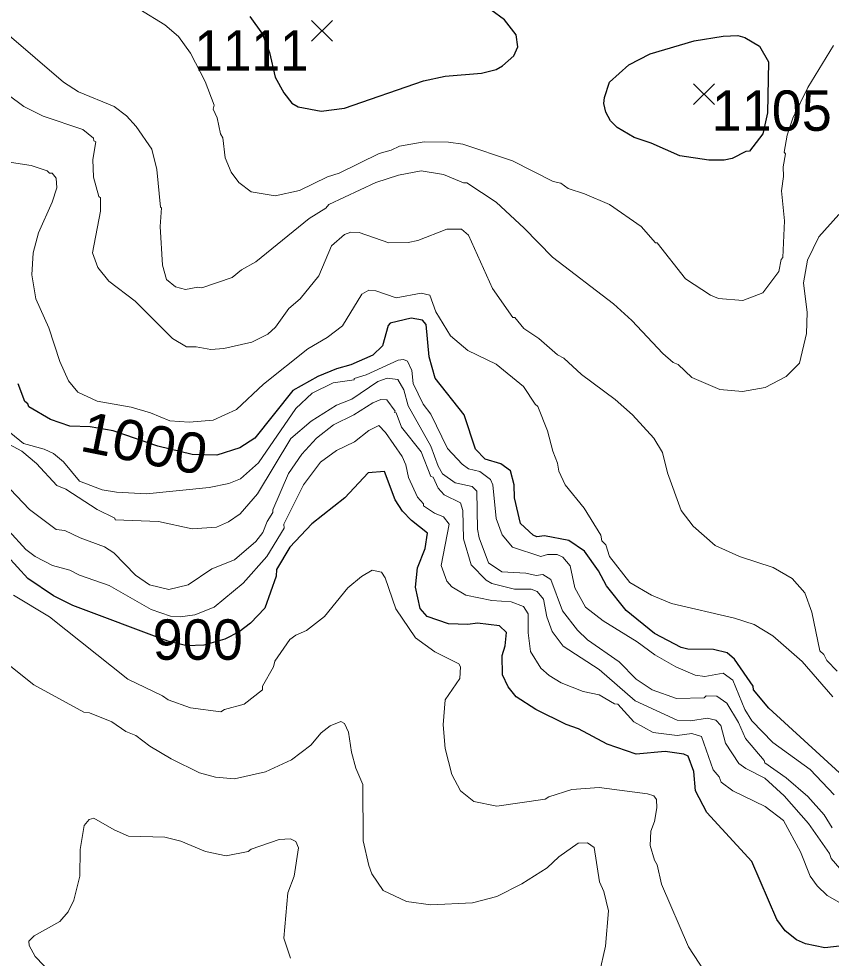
# Model space of a CAD drawing. Extents: x 265.7 to 292.1, y 7676.2 to 7704.2.
# Drawn here: x 267.081 to 268.69, y 7696.571 to 7698.433 of the extents above; entities that cross this region are included whole.
import ezdxf
from ezdxf.enums import TextEntityAlignment as Align

# ---------------------------------------------------------------- set-up
doc = ezdxf.new("R2010")
doc.units = 0
doc.header["$LTSCALE"] = 0.032
for name, color, linetype, lineweight in [('1', 7, 'Continuous', 25), ('2', 7, 'Continuous', 13), ('21', 7, 'Continuous', 25)]:
    doc.layers.add(name, color=color, linetype=linetype, lineweight=lineweight)
doc.layers.add('61', color=7, linetype='Continuous')

msp = doc.modelspace()

# ---------------------------------------------------------------- linework, layer by layer
at = {"layer": '1'}
for points in [[(267.5381, 7698.4374), (267.5632, 7698.4023), (267.5774, 7698.3663), (267.5883, 7698.317), (267.6052, 7698.2862), (267.6212, 7698.2654), (267.634, 7698.2583), (267.6795, 7698.2495), (267.7257, 7698.2559), (267.8821, 7698.3101), (267.9252, 7698.3189), (267.9971, 7698.3253), (268.0258, 7698.3325), (268.0385, 7698.3397), (268.0609, 7698.3596), (268.0689, 7698.3772), (268.0657, 7698.4011), (268.0425, 7698.4306), (268.0154, 7698.4506)], [(268.7064, 7696.9384), (268.566, 7697.0661), (268.5357, 7697.1028), (268.5349, 7697.11), (268.4982, 7697.1635), (268.4838, 7697.1762), (268.4567, 7697.1826), (268.4056, 7697.1834), (268.3928, 7697.1866), (268.3394, 7697.2145), (268.2835, 7697.26), (268.2444, 7697.3087), (268.2285, 7697.3382), (268.2013, 7697.3773), (268.1702, 7697.3989), (268.1215, 7697.4076), (268.1064, 7697.406), (268.0992, 7697.4092), (268.0745, 7697.4324), (268.0625, 7697.4835), (268.0617, 7697.509), (268.0545, 7697.5369), (268.0354, 7697.5505), (268.0042, 7697.5601), (267.9851, 7697.58), (267.9627, 7697.6478), (267.9053, 7697.7205), (267.8933, 7697.7627), (267.8877, 7697.8266), (267.8805, 7697.8353), (267.8574, 7697.8393), (267.8159, 7697.8298), (267.8119, 7697.825), (267.8007, 7697.7843), (267.7816, 7697.7659), (267.7385, 7697.7468), (267.7098, 7697.7388), (267.6731, 7697.7236), (267.6236, 7697.6957), (267.5478, 7697.6016), (267.5183, 7697.5824), (267.4728, 7697.568), (267.4237, 7697.5689), (267.3559, 7697.5859), (267.2673, 7697.6161), (267.2221, 7697.6237), (267.1815, 7697.6255), (267.1432, 7697.6382), (267.1001, 7697.6638), (267.0985, 7697.6694), (267.0922, 7697.6742), (267.0794, 7697.7093)], [(268.7344, 7696.5977), (268.6769, 7696.5913), (268.6386, 7696.5993), (268.6211, 7696.6073), (268.5987, 7696.6248), (268.5819, 7696.6472), (268.5325, 7696.7621), (268.4431, 7696.8594), (268.4208, 7696.9025), (268.4176, 7696.9408), (268.4064, 7696.9712), (268.3976, 7696.9752), (268.3609, 7696.9807), (268.3035, 7696.9751), (268.246, 7696.9951), (268.1894, 7697.0254), (268.1646, 7697.0342), (268.1048, 7697.0637), (268.0657, 7697.0885), (268.0497, 7697.1084), (268.0385, 7697.1324), (268.0377, 7697.1707), (268.0441, 7697.1898), (268.0465, 7697.2161), (268.033, 7697.2297), (267.9891, 7697.2345), (267.9699, 7697.2321), (267.9316, 7697.2337), (267.8893, 7697.248), (267.8758, 7697.264), (267.8662, 7697.3063), (267.8702, 7697.3446), (267.8853, 7697.3829), (267.8901, 7697.4132), (267.8582, 7697.438), (267.8406, 7697.4571), (267.8263, 7697.4795), (267.8047, 7697.5353), (267.7728, 7697.5329), (267.7265, 7697.4835), (267.6611, 7697.4316), (267.6172, 7697.3853), (267.5909, 7697.3414), (267.5901, 7697.3279), (267.5677, 7697.2648), (267.5396, 7697.2349), (267.517, 7697.2179), (267.4887, 7697.2028), (267.4473, 7697.1915), (267.4133, 7697.1896), (267.3757, 7697.199), (267.1879, 7697.2696), (267.1496, 7697.2887), (267.0985, 7697.3231), (267.0363, 7697.3909)]]:
    msp.add_lwpolyline(points, dxfattribs=at)
msp.add_lwpolyline([(268.5634, 7698.2464), (268.5543, 7698.2047), (268.5277, 7698.1705), (268.5205, 7698.1697), (268.4934, 7698.1561), (268.4774, 7698.1529), (268.4471, 7698.1529), (268.3897, 7698.1609), (268.333, 7698.1864), (268.2995, 7698.1976), (268.266, 7698.2176), (268.2524, 7698.2303), (268.2436, 7698.2479), (268.2396, 7698.2647), (268.2404, 7698.2766), (268.2508, 7698.307), (268.2891, 7698.3413), (268.3314, 7698.3636), (268.4184, 7698.3891), (268.4758, 7698.3987), (268.5046, 7698.3995), (268.5189, 7698.3955), (268.5476, 7698.3788), (268.5652, 7698.3476)], close=True, dxfattribs=at)
at = {"layer": '2'}
for points in [[(267.3906, 7697.9016), (267.373, 7697.916), (267.3651, 7697.9447), (267.3603, 7698.0213), (267.3635, 7698.058), (267.3611, 7698.0596), (267.3539, 7698.1338), (267.3443, 7698.1745), (267.3132, 7698.2192), (267.294, 7698.2407), (267.2693, 7698.2591), (267.1991, 7698.2878), (267.1688, 7698.307), (267.057, 7698.4035), (267.0124, 7698.4378)], [(267.6364, 7698.0923), (267.5885, 7698.0819), (267.5406, 7698.0899), (267.5167, 7698.1083), (267.5015, 7698.129), (267.4895, 7698.1569), (267.4848, 7698.1968), (267.48, 7698.2048), (267.4736, 7698.2367), (267.4656, 7698.2535), (267.4672, 7698.2615), (267.4496, 7698.3086), (267.4209, 7698.3644), (267.397, 7698.3979), (267.3699, 7698.4211), (267.3204, 7698.4514)], [(268.6945, 7698.3796), (268.6434, 7698.2966), (268.6134, 7698.2361), (268.6022, 7698.2023), (268.5965, 7698.1686), (268.5995, 7698.1649), (268.5947, 7698.1394), (268.5955, 7698.1202), (268.5915, 7698.0915), (268.5971, 7698.0325), (268.5939, 7697.9598), (268.5907, 7697.9559), (268.5859, 7697.9319), (268.554, 7697.8896), (268.5149, 7697.8745), (268.4663, 7697.8784), (268.4503, 7697.8848), (268.4008, 7697.9175), (268.345, 7697.9886), (268.3418, 7697.9886), (268.313, 7698.0213), (268.2508, 7698.0644), (268.2013, 7698.0859), (268.1686, 7698.0963), (268.1542, 7698.1067), (268.1391, 7698.1106), (268.0585, 7698.1513), (267.9603, 7698.1841), (267.9316, 7698.1881), (267.8837, 7698.1888)], [(268.7017, 7697.1395), (268.6809, 7697.1611), (268.6753, 7697.173), (268.6673, 7697.1802), (268.6514, 7697.2568), (268.6378, 7697.2951), (268.6123, 7697.3231), (268.5748, 7697.3454), (268.5078, 7697.367), (268.4599, 7697.3885), (268.416, 7697.4268), (268.3928, 7697.4579), (268.3657, 7697.5329), (268.3553, 7697.5728), (268.3386, 7697.6016), (268.2963, 7697.6478), (268.262, 7697.6782), (268.1949, 7697.7276), (268.1598, 7697.7603), (268.1479, 7697.7667), (268.1104, 7697.7994), (268.0808, 7697.8186), (268.0633, 7697.8409), (268.0593, 7697.8409), (268.0186, 7697.8984), (267.9715, 7698.0037), (267.9572, 7698.0157), (267.9284, 7698.0157), (267.871, 7697.9933), (267.8518, 7697.9894), (267.8135, 7697.9886), (267.7545, 7698.0093), (267.7385, 7698.0101), (267.7257, 7698.0053), (267.7002, 7697.983), (267.6747, 7697.9231), (267.638, 7697.8776), (267.6156, 7697.8585), (267.5893, 7697.8218), (267.5741, 7697.8074), (267.5422, 7697.7915), (267.4864, 7697.7795), (267.4608, 7697.7771), (267.4321, 7697.7827), (267.4129, 7697.7827), (267.385, 7697.7994), (267.3108, 7697.8729), (267.2589, 7697.9128), (267.2374, 7697.9399), (267.2262, 7697.9686), (267.2422, 7698.0516), (267.2422, 7698.0779), (267.239, 7698.0803), (267.2286, 7698.1186), (267.227, 7698.1537), (267.2334, 7698.1889), (267.2294, 7698.1912), (267.2286, 7698.196), (267.2071, 7698.2136), (267.1289, 7698.2399), (267.0906, 7698.2591), (267.0275, 7698.3054)], [(267.8837, 7698.1888), (267.8343, 7698.1801), (267.8183, 7698.1721), (267.7944, 7698.1657), (267.7154, 7698.1266), (267.6922, 7698.1194), (267.6364, 7698.0923)], [(268.2436, 7697.3901), (268.2356, 7697.3981), (268.2332, 7697.4092), (268.2005, 7697.4627), (268.163, 7697.509), (268.1503, 7697.5361), (268.1479, 7697.5521), (268.1383, 7697.576), (268.1279, 7697.6159), (268.1088, 7697.6646), (268.1032, 7697.6686), (268.08, 7697.7037), (268.0258, 7697.7484), (267.9699, 7697.7755), (267.9356, 7697.8042), (267.9069, 7697.8521), (267.8949, 7697.8848), (267.8774, 7697.8888), (267.8279, 7697.88), (267.788, 7697.8936), (267.7736, 7697.8952), (267.7601, 7697.8872), (267.7217, 7697.8242), (267.6914, 7697.801), (267.6531, 7697.7787), (267.5654, 7697.7085), (267.5119, 7697.6582), (267.4656, 7697.6375), (267.4177, 7697.6335), (267.3794, 7697.6359), (267.3411, 7697.6518), (267.3028, 7697.663), (267.2358, 7697.675), (267.1975, 7697.6925), (267.1791, 7697.7149), (267.1616, 7697.7532), (267.14, 7697.8202), (267.1145, 7697.8777), (267.1065, 7697.9255), (267.1089, 7697.9686), (267.1193, 7698.0085), (267.1464, 7698.0692), (267.156, 7698.0979), (267.1544, 7698.117), (267.1464, 7698.1266), (267.1416, 7698.1266), (267.1368, 7698.1314), (267.1049, 7698.1418), (267.0491, 7698.1505)], [(268.7048, 7698.0452), (268.6649, 7698.0005), (268.6426, 7697.9543), (268.6346, 7697.9096), (268.6418, 7697.8505), (268.641, 7697.809), (268.6266, 7697.75), (268.6003, 7697.7236), (268.5588, 7697.7021), (268.5141, 7697.6941), (268.4694, 7697.6981), (268.4136, 7697.722), (268.3865, 7697.7476), (268.3769, 7697.7516), (268.3561, 7697.7691), (268.2947, 7697.8346), (268.2588, 7697.8681), (268.1375, 7697.9606), (268.0816, 7698.0181), (268.0258, 7698.0692), (267.9683, 7698.1075), (267.9611, 7698.1075), (267.922, 7698.1242), (267.8774, 7698.1314), (267.8327, 7698.1226), (267.788, 7698.1083), (267.6946, 7698.0644), (267.689, 7698.0572), (267.6555, 7698.0372), (267.5502, 7697.9511)], [(267.5502, 7697.9511), (267.5215, 7697.9351), (267.5031, 7697.9199), (267.4433, 7697.8992), (267.4353, 7697.9008), (267.4106, 7697.896), (267.3906, 7697.9016)], [(267.7449, 7697.7173), (267.7449, 7697.7197), (267.7688, 7697.7268), (267.8319, 7697.7564), (267.8423, 7697.7572), (267.8502, 7697.754), (267.859, 7697.7356)], [(267.859, 7697.7356), (267.8614, 7697.7101), (267.8813, 7697.6686), (267.8965, 7697.6494), (267.93, 7697.5808), (267.9587, 7697.5497), (267.9715, 7697.5409), (267.9939, 7697.5353), (268.0146, 7697.5194), (268.0194, 7697.509), (268.0258, 7697.442), (268.0377, 7697.41), (268.0585, 7697.3853), (268.1143, 7697.3669), (268.1279, 7697.3709), (268.1471, 7697.3709), (268.1582, 7697.3654), (268.1726, 7697.3486), (268.1822, 7697.3047), (268.2029, 7697.2664), (268.238, 7697.2393), (268.3051, 7697.1978), (268.3402, 7697.1722), (268.3817, 7697.1483), (268.42, 7697.1316), (268.4391, 7697.1292), (268.4758, 7697.1355), (268.495, 7697.122), (268.5189, 7697.0637), (268.5325, 7697.0414), (268.574, 7696.9983), (268.6482, 7696.9448), (268.6953, 7696.8946)], [(268.6913, 7696.8291), (268.6761, 7696.8547), (268.6434, 7696.8914), (268.6003, 7696.9281), (268.558, 7696.9576), (268.5572, 7696.9624), (268.5197, 7697.0063), (268.5061, 7697.0382), (268.483, 7697.0765), (268.4631, 7697.0901), (268.4423, 7697.0909), (268.4383, 7697.0869), (268.3833, 7697.0853), (268.3354, 7697.1028), (268.3035, 7697.1236), (268.2699, 7697.1579), (268.2069, 7697.2018), (268.187, 7697.2209), (268.1574, 7697.2592), (268.1343, 7697.3215), (268.1183, 7697.331), (268.1056, 7697.3294), (268.0848, 7697.3342), (268.037, 7697.3366), (268.0106, 7697.3542), (267.9923, 7697.4037), (267.9891, 7697.4212), (267.9875, 7697.4962), (267.9787, 7697.5058), (267.9452, 7697.513), (267.9196, 7697.5305), (267.9109, 7697.5457), (267.8965, 7697.5856), (267.8518, 7697.6654), (267.843, 7697.6973), (267.8311, 7697.7181), (267.8103, 7697.7204), (267.792, 7697.7141), (267.7401, 7697.679), (267.7098, 7697.667), (267.6595, 7697.6351), (267.6196, 7697.6007), (267.5534, 7697.4914), (267.5191, 7697.4515), (267.4959, 7697.4356), (267.472, 7697.4252), (267.4241, 7697.422), (267.3571, 7697.4364), (267.2717, 7697.4396), (267.2709, 7697.4428), (267.2358, 7697.4603), (267.1736, 7697.5002), (267.156, 7697.5074), (267.1153, 7697.5513), (267.0866, 7697.576), (267.061, 7697.5896)], [(267.065, 7697.6111), (267.0898, 7697.5912), (267.1305, 7697.58), (267.1496, 7697.5712), (267.1688, 7697.5545), (267.2007, 7697.5162), (267.2454, 7697.4994), (267.2741, 7697.4946), (267.3332, 7697.4914), (267.4576, 7697.5034), (267.4967, 7697.5114), (267.5199, 7697.521), (267.555, 7697.5529), (267.6292, 7697.6606), (267.6619, 7697.6909), (267.7034, 7697.7109), (267.7449, 7697.7173)], [(267.7042, 7697.6279), (267.7441, 7697.6478), (267.7816, 7697.6718), (267.7976, 7697.6782), (267.8095, 7697.6774), (267.8263, 7697.655), (267.8247, 7697.6526), (267.8279, 7697.6518), (267.8383, 7697.6231), (267.8774, 7697.5744), (267.8965, 7697.5257), (267.9013, 7697.5242), (267.9109, 7697.5026), (267.9228, 7697.489), (267.9556, 7697.4731), (267.9603, 7697.4579), (267.9611, 7697.4021), (267.9763, 7697.3502), (268.0066, 7697.3199), (268.0178, 7697.3135), (268.0625, 7697.3023), (268.0952, 7697.3023), (268.1072, 7697.2975), (268.1199, 7697.2824), (268.1263, 7697.2473), (268.1367, 7697.2185), (268.159, 7697.189), (268.2301, 7697.1427), (268.3011, 7697.0805), (268.3849, 7697.0422), (268.412, 7697.0414), (268.4439, 7697.0462), (268.4615, 7697.0422), (268.471, 7697.0318), (268.4806, 7696.9967), (268.5069, 7696.9568), (268.5205, 7696.9464), (268.558, 7696.9273), (268.5963, 7696.8922), (268.645, 7696.8379), (268.6865, 7696.7781), (268.6897, 7696.7685), (268.72, 7696.7334)], [(268.7479, 7696.6576), (268.6817, 7696.6951), (268.6618, 7696.7142), (268.6482, 7696.7334), (268.629, 7696.7813), (268.5955, 7696.8435), (268.5588, 7696.8714), (268.495, 7696.9025), (268.4718, 7696.9193), (268.4678, 7696.9305), (268.4559, 7696.944), (268.4327, 7697.0103), (268.4136, 7697.0158), (268.3849, 7697.0119), (268.337, 7697.0182), (268.2987, 7697.039), (268.2668, 7697.0741), (268.2604, 7697.0749), (268.2301, 7697.0924), (268.1981, 7697.0996), (268.1551, 7697.1164), (268.1311, 7697.1308), (268.1143, 7697.1459), (268.0944, 7697.1786), (268.0896, 7697.2153), (268.0896, 7697.2536), (268.08, 7697.268), (268.0561, 7697.2768), (268.0178, 7697.28), (267.9659, 7697.2903), (267.938, 7697.3071), (267.9284, 7697.3183), (267.9173, 7697.3494), (267.9332, 7697.4308), (267.922, 7697.4459), (267.9037, 7697.4531), (267.8821, 7697.4675), (267.8821, 7697.4715), (267.8702, 7697.4843), (267.8526, 7697.5234), (267.847, 7697.5489), (267.8398, 7697.5649), (267.8071, 7697.6127), (267.7936, 7697.6263), (267.7736, 7697.6167), (267.7457, 7697.5944), (267.7098, 7697.5768), (267.6779, 7697.5537), (267.6443, 7697.509), (267.6052, 7697.4308), (267.606, 7697.4228), (267.5717, 7697.367), (267.5247, 7697.3143), (267.4672, 7697.2664), (267.4289, 7697.2512)], [(267.5725, 7697.4364), (267.5837, 7697.4539), (267.5837, 7697.4595), (267.6148, 7697.5313), (267.6412, 7697.5696), (267.6699, 7697.6016), (267.7042, 7697.6279)], [(267.0507, 7697.5138), (267.1017, 7697.4603), (267.1544, 7697.4204), (267.172, 7697.4188), (267.2023, 7697.4037), (267.2502, 7697.3861), (267.2685, 7697.3741), (267.3116, 7697.3302), (267.3395, 7697.3111), (267.3778, 7697.3015), (267.4161, 7697.3111), (267.4632, 7697.3422), (267.5079, 7697.3606), (267.5502, 7697.3965), (267.5638, 7697.4148), (267.5725, 7697.4364)], [(267.1815, 7697.3398), (267.1472, 7697.3494), (267.1129, 7697.3669), (267.0946, 7697.3805), (267.061, 7697.418)], [(268.5373, 7697.2321), (268.4982, 7697.2449), (268.3737, 7697.2736), (268.3338, 7697.2903), (268.2907, 7697.3151), (268.2508, 7697.367), (268.2436, 7697.3901)], [(267.4289, 7697.2512), (267.4002, 7697.2472), (267.381, 7697.2488), (267.3427, 7697.2616), (267.2597, 7697.3095), (267.2007, 7697.3302), (267.1815, 7697.3398)], [(267.6172, 7697.2026), (267.6292, 7697.2113), (267.6507, 7697.2201), (267.6859, 7697.248), (267.7321, 7697.3047), (267.7593, 7697.3271), (267.7808, 7697.3398)], [(267.7808, 7697.3398), (267.7992, 7697.3358), (267.8063, 7697.3247), (267.8271, 7697.2632), (267.8662, 7697.2058), (267.9045, 7697.1778), (267.9524, 7697.1539), (267.9556, 7697.1483), (267.954, 7697.1252), (267.9252, 7697.0829), (267.9212, 7697.0334), (267.9252, 7696.9863), (267.938, 7696.9345), (267.9556, 7696.9025), (267.9819, 7696.881), (268.0274, 7696.8722), (268.1231, 7696.8858), (268.1303, 7696.8906), (268.1758, 7696.9049), (268.2301, 7696.9089), (268.3258, 7696.8962), (268.3386, 7696.8922), (268.3434, 7696.885), (268.3442, 7696.869), (268.3394, 7696.8419), (268.3322, 7696.8227), (268.3314, 7696.794), (268.3394, 7696.7653), (268.345, 7696.7557), (268.3537, 7696.7174), (268.4072, 7696.5929), (268.4391, 7696.5435)], [(267.0698, 7697.2903), (267.1416, 7697.2473), (267.2964, 7697.1236), (267.3651, 7697.0909), (267.3762, 7697.0829), (267.4209, 7697.0669), (267.4808, 7697.0589), (267.488, 7697.0637), (267.5271, 7697.0741), (267.563, 7697.1028), (267.563, 7697.11), (267.5853, 7697.1483), (267.5877, 7697.1595), (267.6172, 7697.2026)], [(268.6929, 7697.0885), (268.6322, 7697.1587), (268.574, 7697.2098), (268.5373, 7697.2321)], [(267.0411, 7697.1675), (267.1105, 7697.1124), (267.2095, 7697.0581), (267.2206, 7697.0573), (267.2645, 7697.039), (267.2925, 7697.0198), (267.3124, 7697.0119), (267.3403, 7696.9911), (267.3826, 7696.9656), (267.4385, 7696.9384), (267.4704, 7696.9297), (267.5079, 7696.9265), (267.5693, 7696.94), (267.6204, 7696.964), (267.6587, 7696.9927), (267.6795, 7697.0174), (267.697, 7697.031), (267.7186, 7697.0398), (267.7257, 7697.0358), (267.7337, 7697.019), (267.7393, 7696.9791), (267.7481, 7696.9472), (267.7617, 7696.9153), (267.7625, 7696.8036), (267.7736, 7696.7541), (267.78, 7696.7382), (267.8023, 7696.7046), (267.8486, 7696.6831), (267.8965, 7696.6767), (267.9795, 7696.6807), (268.0274, 7696.6927), (268.0769, 7696.7182), (268.1271, 7696.7501), (268.1503, 7696.7717), (268.1886, 7696.7988), (268.2069, 7696.7996), (268.2205, 7696.79), (268.2309, 7696.7222), (268.2396, 7696.7031), (268.2484, 7696.6647), (268.2428, 7696.5945), (268.2301, 7696.5387)], [(267.164, 7696.5211), (267.1129, 7696.5738), (267.1009, 7696.5961), (267.1001, 7696.6041), (267.1113, 7696.6153), (267.1616, 7696.6432), (267.1783, 7696.6624), (267.1895, 7696.6855), (267.2015, 7696.7334), (267.2023, 7696.786), (267.2103, 7696.8339), (267.2198, 7696.8459), (267.2294, 7696.8483), (267.2693, 7696.8251), (267.298, 7696.8124), (267.3699, 7696.8108), (267.4018, 7696.8028), (267.4504, 7696.782), (267.4911, 7696.7733), (267.535, 7696.782), (267.5406, 7696.7868), (267.5965, 7696.806), (267.6188, 7696.8076), (267.6292, 7696.802), (267.6348, 7696.7892), (267.626, 7696.7334), (267.6132, 7696.6999), (267.6052, 7696.6105), (267.6188, 7696.5706)]]:
    msp.add_lwpolyline(points, dxfattribs=at)
at = {"layer": '21'}
for p, q in [((267.6605, 7698.4296), (267.7017, 7698.3884)), ((267.7017, 7698.4296), (267.6605, 7698.3884)), ((268.4172, 7698.3041), (268.4584, 7698.2629)), ((268.4584, 7698.3041), (268.4172, 7698.2629))]:
    msp.add_line(p, q, dxfattribs=at)

# ---------------------------------------------------------------- texts
at = {"layer": '61', "width": 0.95}
msp.add_text('1111', height=0.08, dxfattribs=at).set_placement((267.5415, 7698.3302), align=Align.CENTER)
at = {"layer": '61'}
for s, p in [('1105', (268.572, 7698.2108)), ('900', (267.435, 7697.1623))]:
    msp.add_text(s, height=0.08, dxfattribs=at).set_placement(p, align=Align.CENTER)
at = {"layer": '61', "width": 1.05}
msp.add_text('1000', height=0.08, rotation=348.619, dxfattribs=at).set_placement((267.3215, 7697.5523), align=Align.CENTER)

doc.saveas('drawing.dxf')
